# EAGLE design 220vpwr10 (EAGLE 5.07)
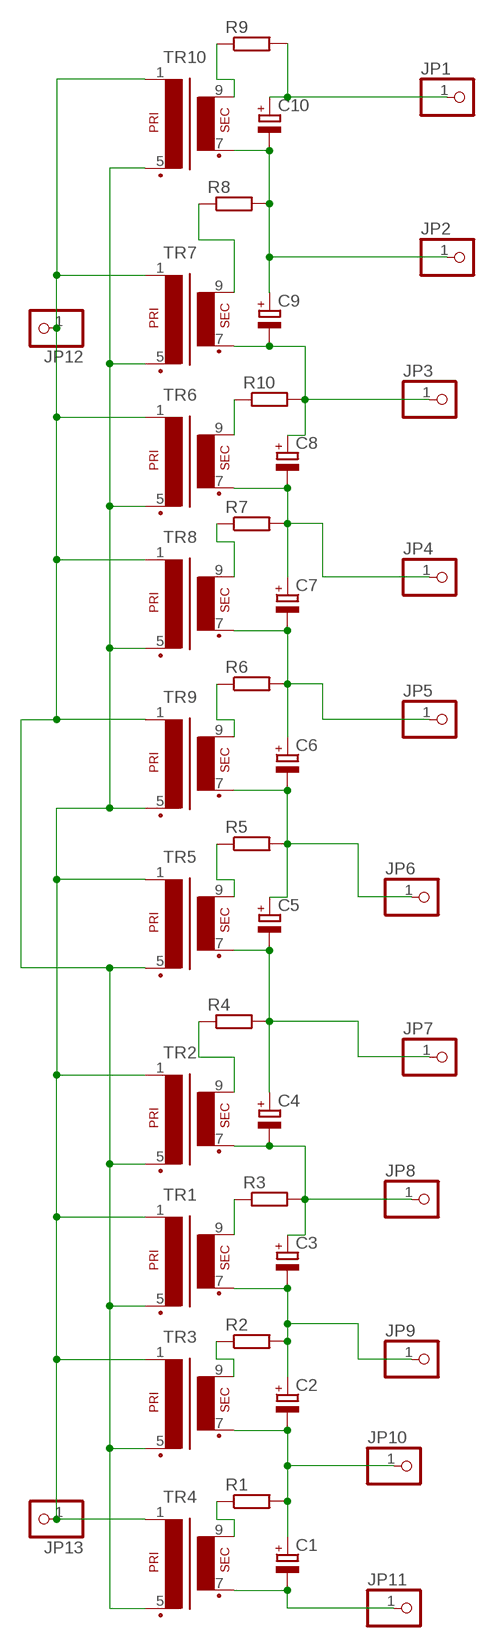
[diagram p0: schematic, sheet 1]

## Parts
C1  CPOL-EUE3.5-8  [E3,5-8]
C2  CPOL-EUE3.5-8  [E3,5-8]
C3  CPOL-EUE3.5-8  [E3,5-8]
C4  CPOL-EUE3.5-8  [E3,5-8]
C5  CPOL-EUE3.5-8  [E3,5-8]
C6  CPOL-EUE3.5-8  [E3,5-8]
C7  CPOL-EUE3.5-8  [E3,5-8]
C8  CPOL-EUE3.5-8  [E3,5-8]
C9  CPOL-EUE3.5-8  [E3,5-8]
C10  CPOL-EUE3.5-8  [E3,5-8]
JP1  PINHD-1X11MM6  [1X1MM8]
JP2  PINHD-1X11MM6  [1X1MM8]
JP3  PINHD-1X11MM6  [1X1MM8]
JP4  PINHD-1X11MM6  [1X1MM8]
JP5  PINHD-1X11MM6  [1X1MM8]
JP6  PINHD-1X11MM6  [1X1MM8]
JP7  PINHD-1X11MM6  [1X1MM8]
JP8  PINHD-1X11MM6  [1X1MM8]
JP9  PINHD-1X11MM6  [1X1MM8]
JP10  PINHD-1X11MM6  [1X1MM8]
JP11  PINHD-1X11MM6  [1X1MM8]
JP12  PINHD-1X11MM6  [1X1MM8]
JP13  PINHD-1X11MM6  [1X1MM8]
R1  R-EU_R1210  [R1210]
R2  R-EU_R1210  [R1210]
R3  R-EU_R1210  [R1210]
R4  R-EU_R1210  [R1210]
R5  R-EU_R1210  [R1210]
R6  R-EU_R1210  [R1210]
R7  R-EU_R1210  [R1210]
R8  R-EU_R1210  [R1210]
R9  R-EU_R1210  [R1210]
R10  R-EU_R1210  [R1210]
TR1  VR11  [1X3WDIRVER]
TR2  VR11  [1X3WDIRVER]
TR3  VR11  [1X3WDIRVER]
TR4  VR11  [1X3WDIRVER]
TR5  VR11  [1X3WDIRVER]
TR6  VR11  [1X3WDIRVER]
TR7  VR11  [1X3WDIRVER]
TR8  VR11  [1X3WDIRVER]
TR9  VR11  [1X3WDIRVER]
TR10  VR11  [1X3WDIRVER]

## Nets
N$1: C1.+ C2.- JP10.1 R1.2 TR3.7(S3)
N$2: C2.+ C3.- JP9.1 R2.2 TR1.7(S3)
N$3: C3.+ C4.- JP8.1 R3.2 TR2.7(S3)
N$4: C4.+ C5.- JP7.1 R4.2 TR5.7(S3)
N$5: JP12.1 TR1.5(P2) TR2.5(P2) TR3.5(P2) TR4.5(P2) TR5.5(P2) TR6.1 TR7.1 TR8.1 TR9.1 TR10.1
N$6: JP13.1 TR1.1 TR2.1 TR3.1 TR4.1 TR5.1 TR6.5(P2) TR7.5(P2) TR8.5(P2) TR9.5(P2) TR10.5(P2)
N$7: C7.+ C8.- JP4.1 R7.2 TR6.7(S3)
N$8: C8.+ C9.- JP3.1 R10.2 TR7.7(S3)
N$9: C6.+ C7.- JP5.1 R6.2 TR8.7(S3)
N$10: C9.+ C10.- JP2.1 R8.2 TR10.7(S3)
N$11: C10.+ JP1.1 R9.2
N$12: C1.- JP11.1 TR4.7(S3)
N$13: C5.+ C6.- JP6.1 R5.2 TR9.7(S3)
N$14: R9.1 TR10.9(S4)
N$15: R8.1 TR7.9(S4)
N$16: R10.1 TR6.9(S4)
N$17: R7.1 TR8.9(S4)
N$18: R6.1 TR9.9(S4)
N$19: R5.1 TR5.9(S4)
N$20: R4.1 TR2.9(S4)
N$21: R3.1 TR1.9(S4)
N$22: R2.1 TR3.9(S4)
N$23: R1.1 TR4.9(S4)

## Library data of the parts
C1-C10 = rcl:CPOL-EU: POLARIZED CAPACITOR, European symbol
JP1-JP13 = pinhead:PINHD-1X1: PIN HEADER
R1-R10 = rcl:R-EU_: RESISTOR, European symbol
TR1-TR10 = trafo:VR11: TRANSFORMER 1 primary winding, 1 secondary winding BLOCK

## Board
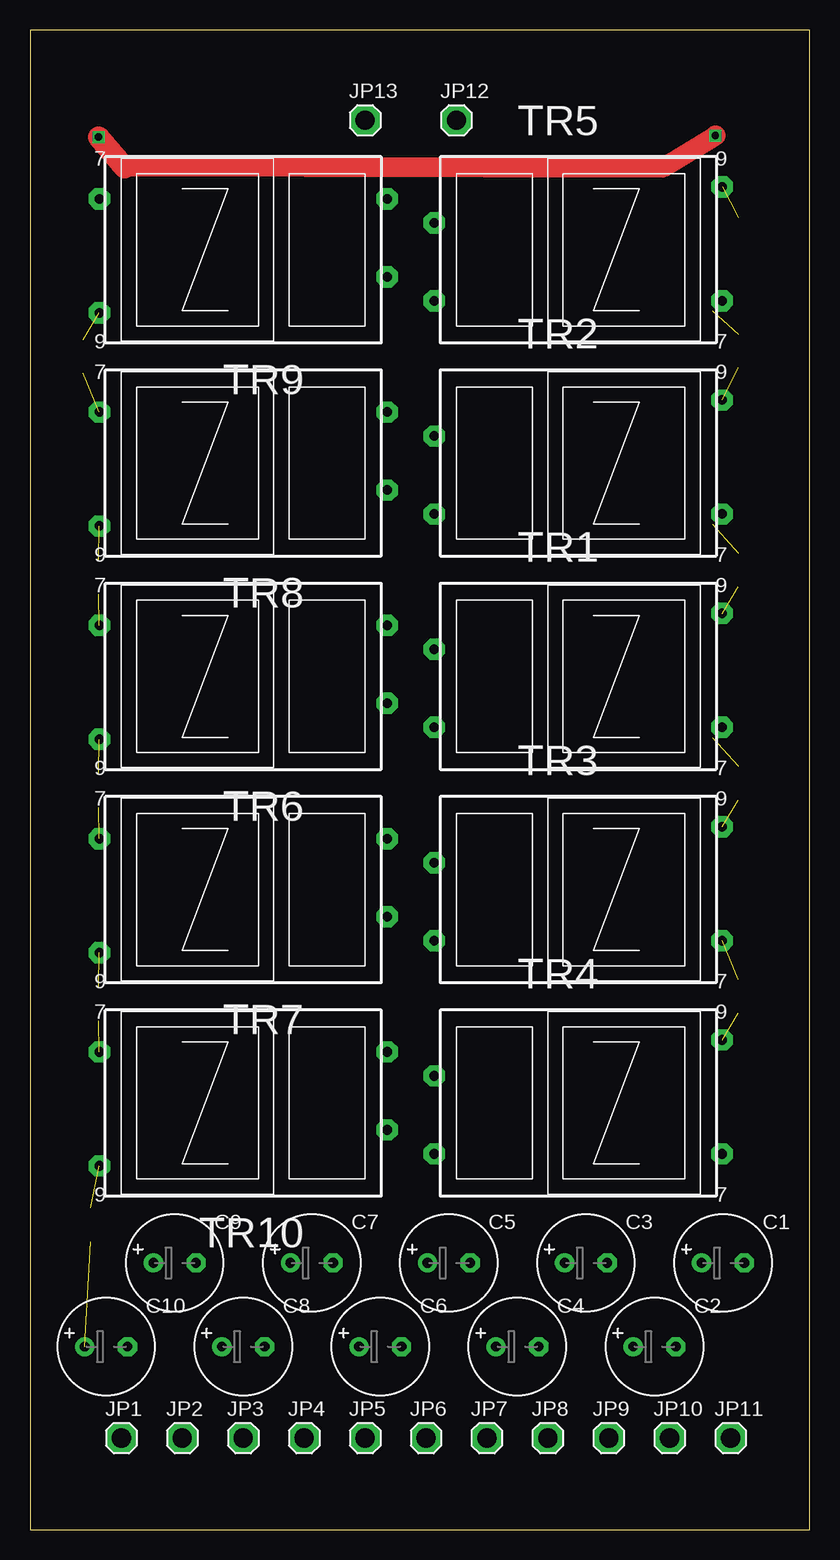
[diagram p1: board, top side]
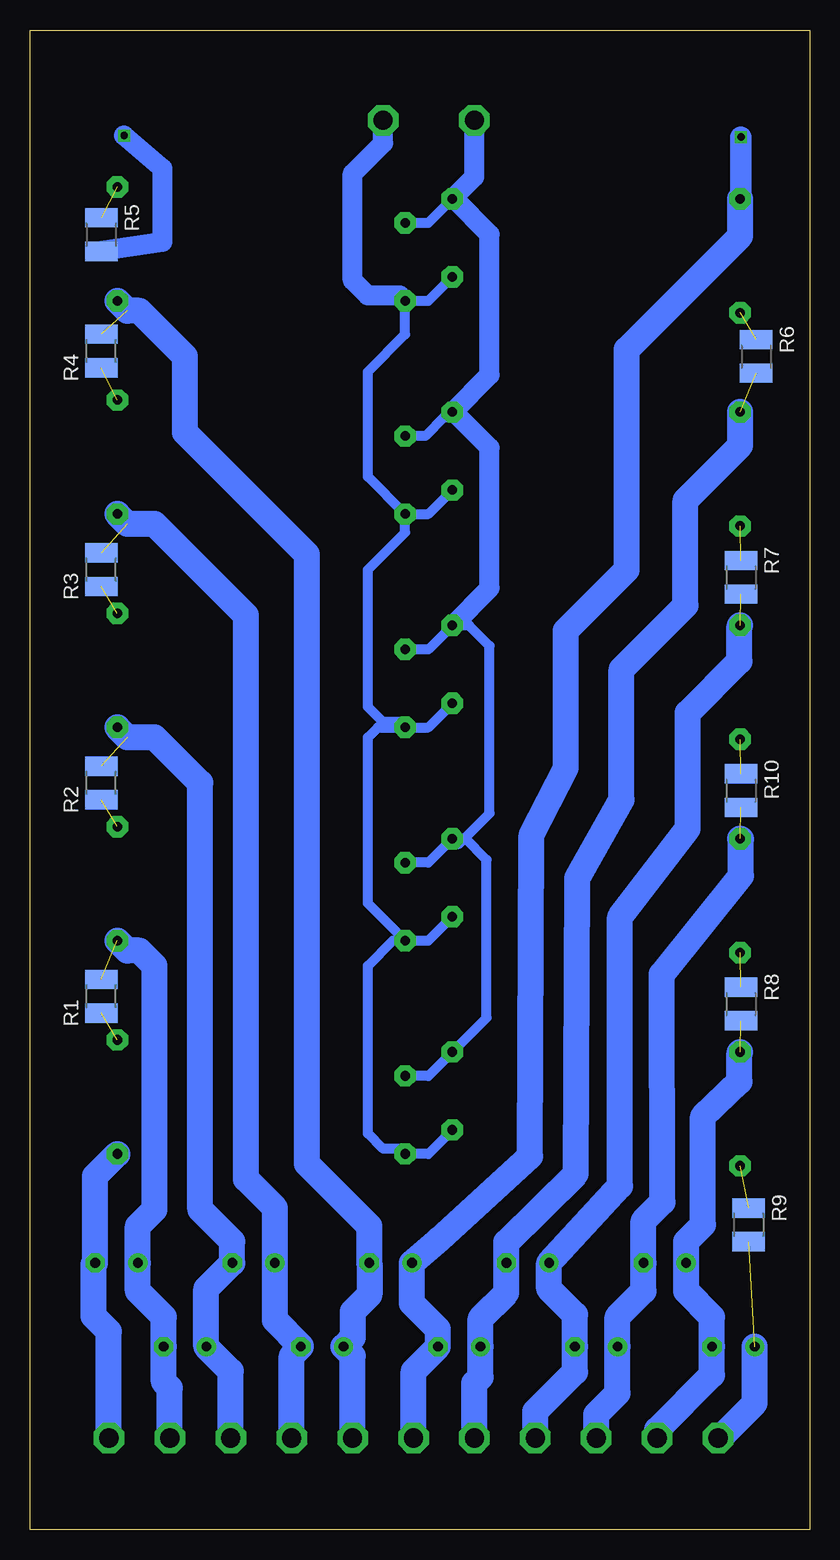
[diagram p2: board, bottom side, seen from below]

Size 65 x 125 mm. Coordinates in mm from the lower left corner, seen from the top.
Outline: 0,0 65,0 65,125 0,125 0,0
Copper layers (1*16): Top 0.035mm / dielectric 1.5mm / Bottom 0.035mm
Design rules "default": minimum track width 10mil, minimum drill 20mil, track to track 8mil, track to pad 8mil, pad to pad 8mil, via to via 8mil, smd to smd 8mil, copper to edge 40mil, drill to drill 8mil, minimum pad ring 1mil, minimum via ring 8mil, stop-mask expansion 4mil, vias tented up to drill 0mil, thermal gap 10mil

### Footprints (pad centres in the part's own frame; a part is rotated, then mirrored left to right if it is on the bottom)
E3,5-8 = drill 0.813 pad 1.6 round: + -1.778,0 | drill 0.813 pad 1.6 octagon: - 1.778,0
1X1MM8 = drill 1.6 pad 2.54 octagon: 1 0,0
R1210 = smd 1.6 x 2.7: 1 -1.4,0; 2 1.4,0
1X3WDIRVER = drill 0.8 pad 1.778 octagon: 1 -12,2.25; 5 -12,-4.25; 7 12,-4.25; 9 12,5.25

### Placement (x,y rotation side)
C1  57.78,22.23 0 top
C2  52.07,15.24 0 top
C3  46.35,22.23 0 top
C4  40.64,15.24 0 top
C5  34.92,22.23 0 top
C6  29.21,15.24 0 top
C7  23.5,22.23 0 top
C8  17.78,15.24 0 top
C9  12.06,22.23 0 top
C10  6.35,15.24 0 top
JP1  7.62,7.62 0 top
JP2  12.7,7.62 0 top
JP3  17.78,7.62 0 top
JP4  22.86,7.62 0 top
JP5  27.94,7.62 0 top
JP6  33.02,7.62 0 top
JP7  38.1,7.62 0 top
JP8  43.18,7.62 0 top
JP9  48.26,7.62 0 top
JP10  53.34,7.62 0 top
JP11  58.42,7.62 0 top
JP12  35.56,117.47 0 top
JP13  27.94,117.47 0 top
R1  59.05,44.45 90 bottom
R2  59.05,62.23 90 bottom
R3  59.05,80.01 90 bottom
R4  59.05,98.23 90 bottom
R5  59.05,107.95 270 bottom
R6  4.45,97.79 270 bottom
R7  5.71,79.38 270 bottom
R8  5.71,43.81 270 bottom
R9  5.08,25.4 270 bottom
R10  5.71,61.59 270 bottom
TR1  45.72,71.12 0 top
TR2  45.72,88.9 0 top
TR3  45.72,53.34 0 top
TR4  45.72,35.56 0 top
TR5  45.72,106.68 0 top
TR6  17.78,71.12 180 top
TR7  17.78,53.34 180 top
TR8  17.78,88.9 180 top
TR9  17.78,106.68 180 top
TR10  17.78,35.56 180 top

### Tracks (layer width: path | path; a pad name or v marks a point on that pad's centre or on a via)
N$1  (1 unrouted)
  Bottom 2.184: JP10.1 53.34,11.81 53.85,12.32 C2.- 53.85,17.72 56.01,19.88 C1.+ 56.01,25.27 54.61,26.67 54.61,46.99 55.88,48.26 56.89,48.26 TR3.7
N$2  (1 unrouted)
  Bottom 2.184: JP9.1 48.26,13.21 C2.+ 50.29,20.07 C3.- 48.13,24 50.8,26.67 50.8,62.23 54.61,66.04 56.89,66.04 TR1.7
N$3  (1 unrouted)
  Bottom 2.184: TR2.7 56.89,83.82 54.61,83.82 46.99,76.2 46.99,29.21 44.58,26.8 C3.+ 44.58,17.46 42.42,15.3 C4.- 43.18,14.48 JP8.1
N$4  (1 unrouted)
  Bottom 2.184: TR5.7 56.89,101.6 55.88,101.6 52.07,97.79 52.07,91.44 41.91,81.28 41.91,30.48 36.7,25.27 C5.- 36.7,19.56 38.1,18.16 38.1,16 C4.+ 38.1,14.48 JP7.1
N$5
  Bottom 0.813: TR2.5 36.83,87.76 36.83,96.52 33.72,99.63 TR5.5 31.78,102.43 TR9.1 | TR2.5 33.72,83.12 36.83,80.01 36.83,68.58 35.56,67.31 34.16,67.31 TR1.5 | TR1.5 36,66.87 36.83,66.04 36.83,52.2 TR3.5 | TR3.5 34.73,49.09 36.83,46.99 36.83,33.02 35.56,31.75 34.16,31.75 TR4.5 31.78,31.31 TR10.1 | TR3.5 31.78,49.09 TR7.1 | TR1.5 31.78,66.87 TR6.1 | TR2.5 31.78,84.65 TR8.1
  Bottom 1.676: JP12.1 35.56,115.57 38.1,113.03 38.1,104.14 36.83,102.87 34.16,102.87 TR5.5
N$6
  Bottom 0.813: TR7.5 29.34,57.15 29.21,57.15 26.67,59.69 26.67,73.66 28.38,75.37 TR6.5 31.78,73.37 TR1.1 | TR7.5 28.7,57.59 26.92,55.82 26.92,42.67 TR10.5 31.78,37.81 TR4.1 | TR3.1 31.78,55.59 TR7.5 | TR2.1 32.04,91.15 30.48,92.71 30.22,92.71 TR8.5 | TR5.1 31.78,108.93 TR9.5
  Bottom 1.676: JP13.1 27.94,112.77 TR9.5 29.65,110.93 26.67,107.95 26.67,96.26 TR8.5 29.65,93.15 26.67,90.17 26.67,78.48 TR6.5
N$7  (1 unrouted)
  Bottom 2.184: JP4.1 22.86,9.84 19.56,13.14 C8.- 19.56,17.91 21.72,20.07 C7.+ 15.81,28.64 15.81,51.05 10.16,58.42 10.16,68.07 5.84,72.39 5.84,75.31 TR6.7
N$8  (1 unrouted)
  Bottom 2.184: JP3.1 17.78,9.59 16,11.37 C8.+ 16,17.72 13.84,19.88 C9.- 13.84,25.72 12.26,27.3 12.32,46.29 5.71,54.48 5.71,57.52 TR7.7
N$9  (1 unrouted)
  Bottom 2.184: TR8.7 5.78,90.36 10.35,85.79 10.35,77.03 15.68,71.69 15.68,60.83 19.37,54.29 19.49,29.65 25.27,23.94 C7.- 25.27,19.75 27.43,17.59 C6.+ 27.43,12.7 27.94,12.19 JP5.1
N$10  (1 unrouted)
  Bottom 2.184: JP2.1 12.7,8.32 8.13,12.89 C10.- 8.13,17.72 10.29,19.88 C9.+ 10.29,24 8.89,25.4 8.89,34.42 5.84,37.34 5.84,39.75 TR10.7
N$11  (1 unrouted)
  Bottom 2.184: JP1.1 7.49,7.62 4.57,10.54 C10.+
N$12
  Bottom 2.184: JP11.1 58.42,16.51 59.69,17.78 59.69,22.1 C1.- 59.56,29.47 TR4.7
N$13  (via drill 0.6)
  Top 1.676: 7.88,113.67 52.77,113.54 v57.15,116.2
  Top 1.778: v5.71,116.08 7.88,113.54 7.88,113.67
  Bottom 1.676: R5.2 53.98,107.31 53.98,113.47 v57.15,116.2
  Bottom 1.778: TR9.7 5.71,110.93 v5.71,116.08
  Bottom 2.184: TR9.7 5.78,107.82 15.24,98.36 15.24,80.01 20.32,74.93 20.32,63.5 23.18,57.91 23.3,31.11 30.86,24.19 C5.+ 33.15,18.86 30.99,16.7 C6.- 33.02,13.21 JP6.1
N$14  (1 unrouted)
N$15  (1 unrouted)
N$16  (1 unrouted)
N$17  (1 unrouted)
N$18  (1 unrouted)
N$19  (1 unrouted)
N$20  (1 unrouted)
N$21  (1 unrouted)
N$22  (1 unrouted)
N$23  (1 unrouted)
